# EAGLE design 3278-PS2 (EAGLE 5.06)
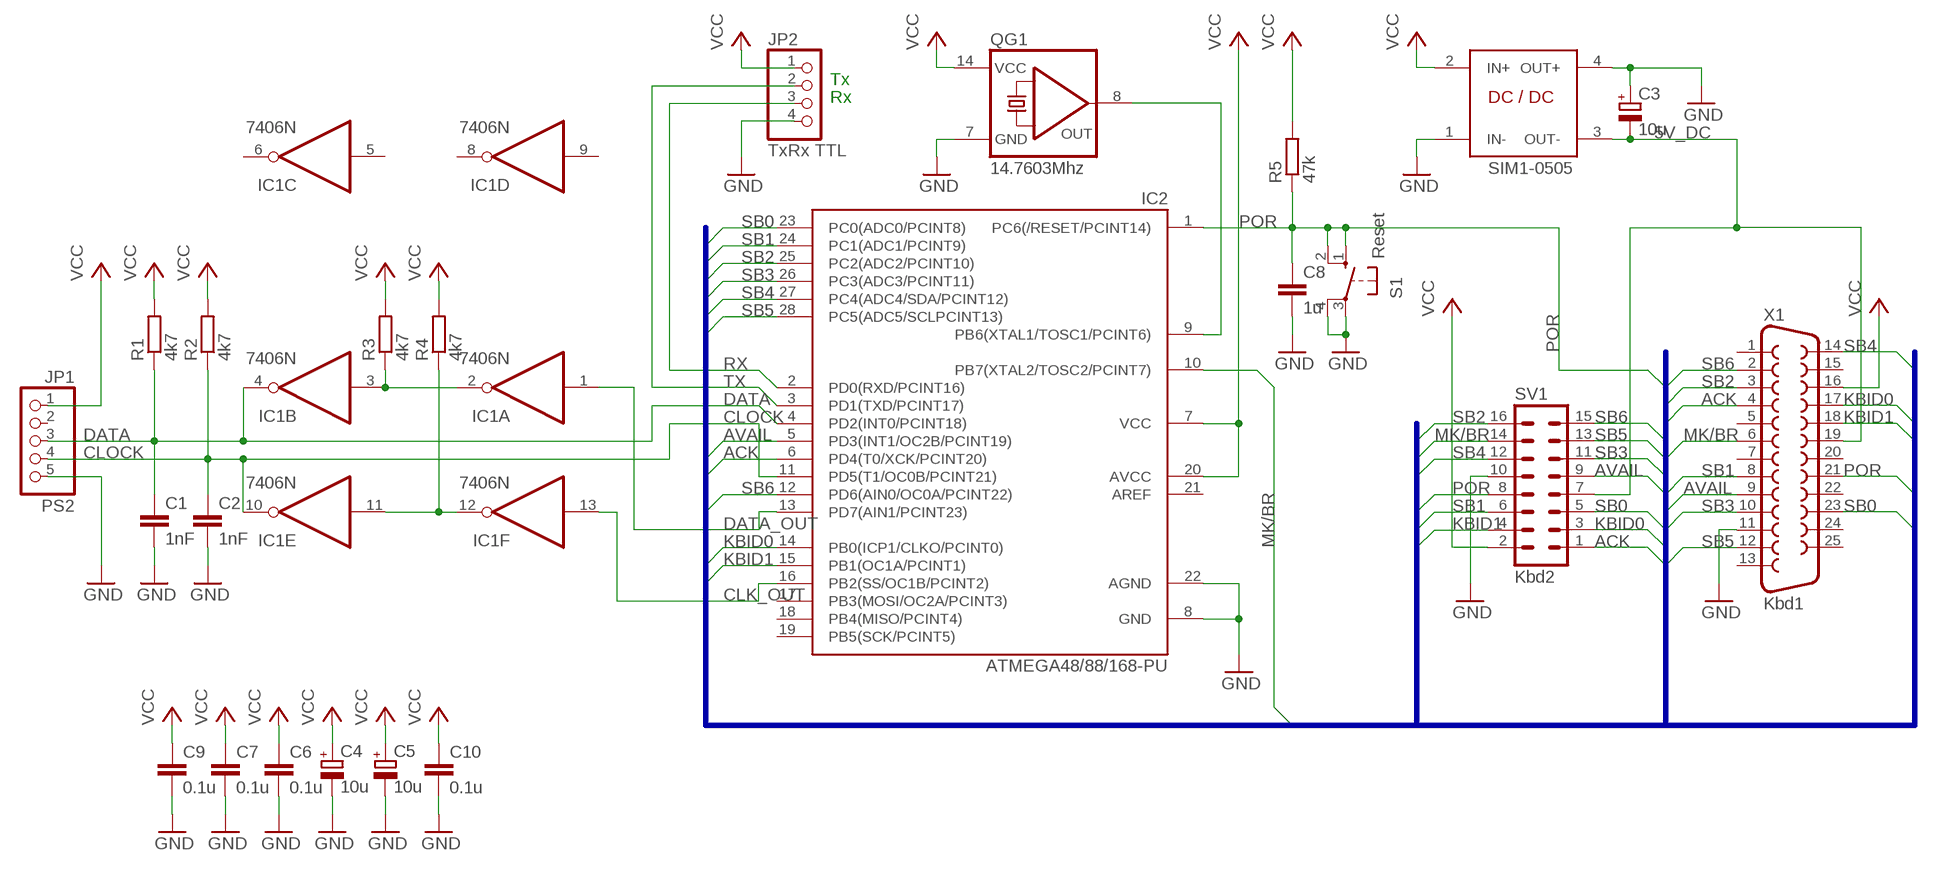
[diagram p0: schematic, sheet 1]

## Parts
C1  1nF  C-EU025_050-025X075  [C025_050-025X075]
C2  1nF  C-EU025_050-025X075  [C025_050-025X075]
C3  10u  CPOL-EUE2.5-7  [E2,5-7]
C4  10u  CPOL-EUE2.5-7  [E2,5-7]
C5  10u  CPOL-EUE2.5-7  [E2,5-7]
C6  0.1u  C-EU025_050-025X075  [C025_050-025X075]
C7  0.1u  C-EU025_050-025X075  [C025_050-025X075]
C8  1u  C-EU025_050-025X075  [C025_050-025X075]
C9  0.1u  C-EU025_050-025X075  [C025_050-025X075]
C10  0.1u  C-EU025_050-025X075  [C025_050-025X075]
IC1  7406N  [DIL14]
IC2  ATMEGA48/88/168-PU  [DIL28-3]
JP1  PS2  PINHD-1X5  [1X05]
JP2  TxRx TTL  PINHD-1X4  [1X04]
QG1  14.7603Mhz  QG5860  [DIL14S]
R1  4k7  R-EU_0207/10  [0207/10]
R2  4k7  R-EU_0207/10  [0207/10]
R3  4k7  R-EU_0207/10  [0207/10]
R4  4k7  R-EU_0207/10  [0207/10]
R5  47k  R-EU_0207/10  [0207/10]
S1  Reset  10-XX  [B3F-10XX]
SV1  Kbd2  ML16  [ML16]
U$1  SIM1-0505  SIM1-SIL4  [SIL4]
X1  Kbd1  F25HP  [F25HP]

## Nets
-5V_DC: C3.- SV1.7 U$1.3(OUT-) X1.19
ACK: IC2.6(PD4(T0/XCK/PCINT20)) SV1.1 X1.4
AVAIL: IC2.5(PD3(INT1/OC2B/PCINT19)) SV1.9 X1.9
CLK_OUT: IC1.13(F:I) IC2.16(PB2(SS/OC1B/PCINT2))
CLOCK: C2.1 IC1.10(E:O) IC2.11(PD5(T1/OC0B/PCINT21)) JP1.4 R2.1
DATA: C1.1 IC1.4(B:O) IC2.4(PD2(INT0/PCINT18)) JP1.3 R1.1
DATA_OUT: IC1.1(A:I) IC2.13(PD7(AIN1/PCINT23))
GND [power]: C1.2 C2.2 C3.+ C4.- C5.- C6.2 C7.2 C8.2 C9.2 C10.2 IC2.8(GND) IC2.22(AGND) JP1.5 JP2.4 QG1.7(GND) S1.3(P) S1.4(P1) SV1.10 U$1.1(IN-) U$1.4(OUT+) X1.11
KBID0: IC2.14(PB0(ICP1/CLKO/PCINT0)) SV1.3 X1.17
KBID1: IC2.15(PB1(OC1A/PCINT1)) SV1.4 X1.18
MK/BR: IC2.10(PB7(XTAL2/TOSC2/PCINT7)) SV1.14 X1.6
N$3: IC1.2(A:O) IC1.3(B:I) R3.1
N$4: IC1.11(E:I) IC1.12(F:O) R4.1
N$9: IC2.9(PB6(XTAL1/TOSC1/PCINT6)) QG1.8(OUT)
POR: C8.1 IC2.1(PC6(/RESET/PCINT14)) R5.1 S1.1(S) S1.2(S1) SV1.8 X1.21
RX: IC2.2(PD0(RXD/PCINT16)) JP2.3
SB0: IC2.23(PC0(ADC0/PCINT8)) SV1.5 X1.23
SB1: IC2.24(PC1(ADC1/PCINT9)) SV1.6 X1.8
SB2: IC2.25(PC2(ADC2/PCINT10)) SV1.16 X1.3
SB3: IC2.26(PC3(ADC3/PCINT11)) SV1.11 X1.10
SB4: IC2.27(PC4(ADC4/SDA/PCINT12)) SV1.12 X1.14
SB5: IC2.28(PC5(ADC5/SCLPCINT13)) SV1.13 X1.12
SB6: IC2.12(PD6(AIN0/OC0A/PCINT22)) SV1.15 X1.2
TX: IC2.3(PD1(TXD/PCINT17)) JP2.2
VCC [power]: C4.+ C5.+ C6.1 C7.1 C9.1 C10.1 IC2.7(VCC) IC2.20(AVCC) JP1.1 JP2.1 QG1.14(VCC) R1.2 R2.2 R3.2 R4.2 R5.2 SV1.2 U$1.2(IN+) X1.16
Unconnected: IC1.5(C:I) IC1.6(C:O) IC1.8(D:O) IC1.9(D:I) IC2.17(PB3(MOSI/OC2A/PCINT3)) IC2.18(PB4(MISO/PCINT4)) IC2.19(PB5(SCK/PCINT5)) IC2.21(AREF) JP1.2 X1.1 X1.5 X1.7 X1.13 X1.15 X1.20 X1.22 X1.24 X1.25

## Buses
SB[0..6],KBID[0..1],POR,ACK,MK/BR,AVAIL

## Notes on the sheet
- Tx
- Rx

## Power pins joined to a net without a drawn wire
GND: IC1.7(P:GND)
VCC: IC1.14(P:VCC)

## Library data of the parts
C1 C2 C6-C10 = rcl:C-EU: CAPACITOR, European symbol
C3-C5 = rcl:CPOL-EU: POLARIZED CAPACITOR, European symbol
IC1 = 74xx-eu:74*06: Hex INVERTER, open collector high-voltage output
IC2 = atmega8:ATMEGA48/88/168-PU
JP1 = pinhead:PINHD-1X5: PIN HEADER
JP2 = pinhead:PINHD-1X4: PIN HEADER
QG1 = crystal:QG5860: CRYSTAL RESONATOR
R1-R5 = rcl:R-EU_: RESISTOR, European symbol
S1 = switch-omron:10-XX: OMRON SWITCH
SV1 = con-harting-ml:ML16: HARTING
U$1 = hjs:SIM1-SIL4
X1 = con-subd:F25: SUB-D

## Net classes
1 power: width 0.635 mm

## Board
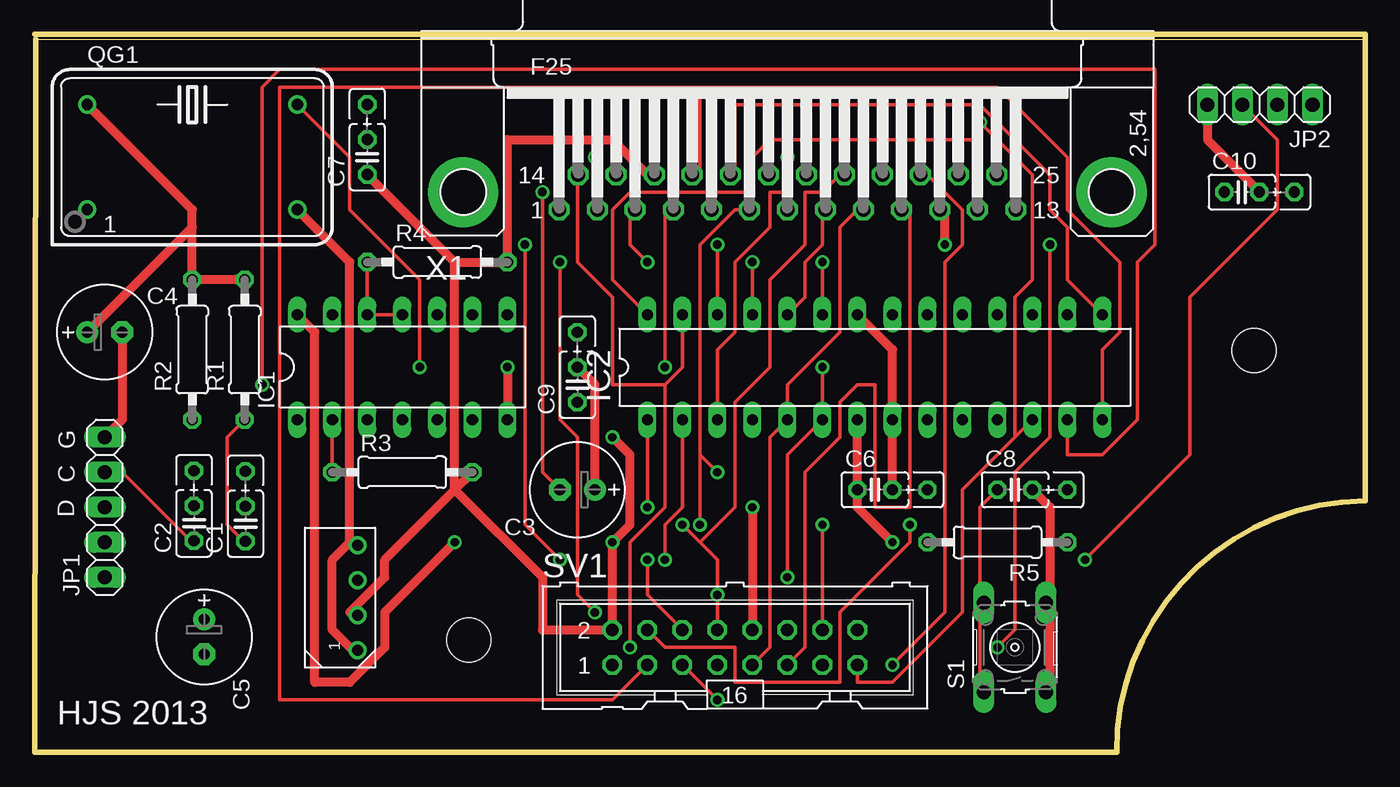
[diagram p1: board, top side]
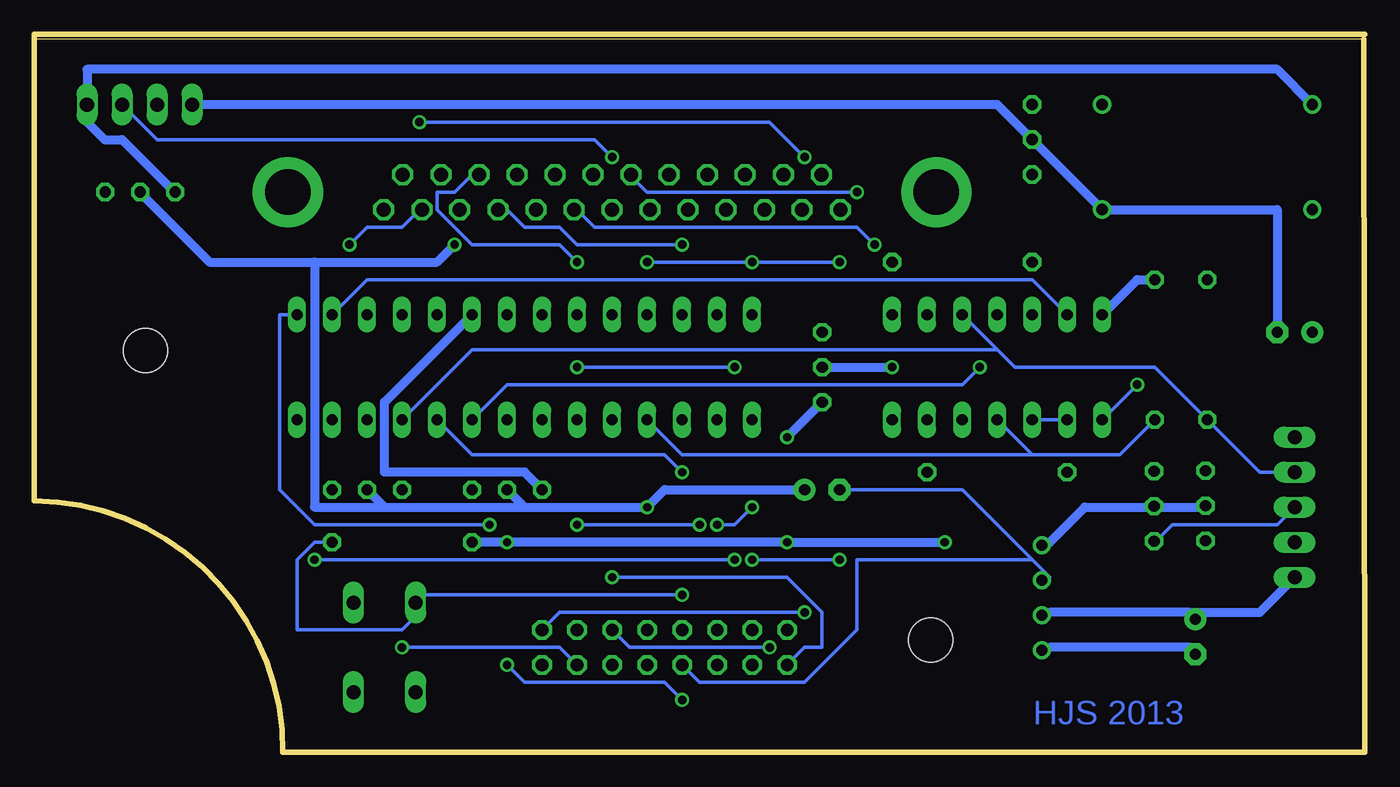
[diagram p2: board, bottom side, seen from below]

Size 96.54 x 52.07 mm. Coordinates in mm from the lower left corner, seen from the top.
Outline: 96.54,51.74 0,51.74 0.09,51.73 0.02,0 78.51,0 arc-90 96.54,18.24 96.54,52.07 0.02,52.07
Copper layers (1*16): Top 0.035mm / dielectric 1.5mm / Bottom 0.035mm
Design rules "default": minimum track width 10mil, minimum drill 24mil, track to track 8mil, track to pad 8mil, pad to pad 8mil, via to via 8mil, smd to smd 8mil, copper to edge 40mil, drill to drill 8mil, minimum pad ring 10mil, minimum via ring 8mil, stop-mask expansion 4mil, vias tented up to drill 0mil, thermal gap 10mil
Holes 3.2 mm at 31.5,8.16 88.5,29.16
tRestrict: area 27.7,4.4 to 35.3,12; area 84.7,25.4 to 92.3,33
bRestrict: area 26.4,0 to 36.6,5.1; area 26.4,3.1 to 36.6,13.2; area 83.4,24.1 to 93.6,34.2; area 91.6,24.2 to 96.7,34.3

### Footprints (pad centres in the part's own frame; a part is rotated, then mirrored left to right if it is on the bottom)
C025_050-025X075 = drill 0.813 octagon: 1 -1.27,0; 2 1.27,0; 3 3.81,0
E2,5-7 = drill 0.813 pad 1.6 round: + -1.27,0 | drill 0.813 pad 1.6 octagon: - 1.27,0
DIL14 = drill 0.813 long: 1 -7.62,-3.81; 2 -5.08,-3.81; 3 -2.54,-3.81; 4 0,-3.81; 5 2.54,-3.81; 6 5.08,-3.81; 7 7.62,-3.81; 8 7.62,3.81; 9 5.08,3.81; 10 2.54,3.81; 11 0,3.81; 12 -2.54,3.81; 13 -5.08,3.81; 14 -7.62,3.81
DIL28-3 = drill 0.813 long: 1 -16.51,-3.81; 2 -13.97,-3.81; 3 -11.43,-3.81; 4 -8.89,-3.81; 5 -6.35,-3.81; 6 -3.81,-3.81; 7 -1.27,-3.81; 8 1.27,-3.81; 9 3.81,-3.81; 10 6.35,-3.81; 11 8.89,-3.81; 12 11.43,-3.81; 13 13.97,-3.81; 14 16.51,-3.81; 15 16.51,3.81; 16 13.97,3.81; 17 11.43,3.81; 18 8.89,3.81; 19 6.35,3.81; 20 3.81,3.81; 21 1.27,3.81; 22 -1.27,3.81; 23 -3.81,3.81; 24 -6.35,3.81; 25 -8.89,3.81; 26 -11.43,3.81; 27 -13.97,3.81; 28 -16.51,3.81
1X05 = drill 1.016 long: 1 -5.08,0; 2 -2.54,0; 3 0,0; 4 2.54,0; 5 5.08,0
1X04 = drill 1.016 long: 1 -3.81,0; 2 -1.27,0; 3 1.27,0; 4 3.81,0
DIL14S = drill 0.813 round: 1 -7.62,-3.81; 7 7.62,-3.81; 8 7.62,3.81; 14 -7.62,3.81
0207/10 = drill 0.813 octagon: 1 -5.08,0; 2 5.08,0
B3F-10XX = drill 1.016 long: 1 -3.251,2.261; 2 3.251,2.261; 3 -3.251,-2.261; 4 3.251,-2.261
ML16 = drill 0.914 octagon: 1 -8.89,-1.27; 2 -8.89,1.27; 3 -6.35,-1.27; 4 -6.35,1.27; 5 -3.81,-1.27; 6 -3.81,1.27; 7 -1.27,-1.27; 8 -1.27,1.27; 9 1.27,-1.27; 10 1.27,1.27; 11 3.81,-1.27; 12 3.81,1.27; 13 6.35,-1.27; 14 6.35,1.27; 15 8.89,-1.27; 16 8.89,1.27
SIL4 = drill 0.8 round: 1 -3.81,0; 2 -1.27,0; 3 1.27,0; 4 3.81,0
F25HP = drill 1.016 octagon: 1 -16.561,-1.27; 2 -13.792,-1.27; 3 -11.049,-1.27; 4 -8.28,-1.27; 5 -5.512,-1.27; 6 -2.769,-1.27; 7 0,-1.27; 8 2.769,-1.27; 9 5.512,-1.27; 10 8.28,-1.27; 11 11.049,-1.27; 12 13.792,-1.27; 13 16.561,-1.27; 14 -15.189,1.27; 15 -12.421,1.27; 16 -9.652,1.27; 17 -6.909,1.27; 18 -4.14,1.27; 19 -1.372,1.27; 20 1.372,1.27; 21 4.14,1.27; 22 6.909,1.27; 23 9.652,1.27; 24 12.421,1.27; 25 15.189,1.27 | drill 3.302 pad 5.08 round: G1 -23.52,0; G2 23.52,0

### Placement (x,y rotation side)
C1  15.31,16.59 90 top
C2  11.57,16.62 90 top
C3  39.39,19.05 180 top
C4  5.1,30.48 0 top
C5  12.31,8.38 270 top
C6  60.98,19.05 0 top
C7  24.15,43.18 90 top
C8  71.14,19.05 0 top
C9  39.39,26.67 90 top
C10  87.6,40.64 0 top
IC1  26.69,27.94 0 top
IC2  60.98,27.94 0 top
JP1  5.1,17.78 90 top
JP2  88.92,46.99 180 top
QG1  11.45,43.18 0 top
R1  15.26,29.21 90 top
R2  11.45,29.21 90 top
R3  26.69,20.32 0 top
R4  29.23,35.56 0 top
R5  69.87,15.24 180 top
S1  71.14,7.62 90 top
SV1  50.82,7.62 0 top
U$1  23.44,11.22 90 top
X1  54.63,40.64 0 top

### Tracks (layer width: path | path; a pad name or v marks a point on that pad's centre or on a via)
-5V_DC  (via drill 0.61)
  Top 0.254: v36.85,40.64 36.85,20.32 C3.-
  Bottom 0.254: 24.15,13.97 29.23,19.05 C3.- | 24.15,13.97 22.88,12.7 U$1.3 | SV1.7 48.28,5.08 40.66,5.08 36.85,8.89 36.85,13.97 24.15,13.97 | v36.85,40.64 52.09,40.64 53.36,41.91 X1.19
ACK  (via drill 0.61)
  Top 0.254: v54.63,12.7 54.63,21.59 IC2.6 v57.17,27.94 | v45.74,27.94 45.74,39.37 X1.4
  Bottom 0.254: v54.63,12.7 41.93,12.7 39.39,10.16 39.39,7.62 40.66,7.62 SV1.1 | v57.17,27.94 v45.74,27.94
AVAIL
  Top 0.254: SV1.9 53.36,7.62 53.36,22.86 IC2.5 54.63,26.67 58.44,30.48 58.44,38.1 59.71,39.37 X1.9
CLK_OUT
  Bottom 0.254: IC1.13 24.15,34.29 72.41,34.29 IC2.16
CLOCK
  Top 0.254: JP1.4 6.37,20.32 11.45,15.24 C2.1
  Bottom 0.254: JP1.4 7.64,20.32 R2.1 15.26,27.94 25.42,27.94 26.69,29.21 | 26.69,29.21 IC1.10 | IC2.11 64.79,29.21 26.69,29.21
DATA
  Top 0.254: R1.1 13.99,22.86 13.99,16.51 15.26,15.24 C1.1
  Bottom 0.254: 24.15,21.59 IC1.4 | 24.15,21.59 17.8,21.59 R1.1 | IC2.4 49.55,21.59 24.15,21.59 | JP1.3 6.37,16.51 13.99,16.51 15.26,15.24 C1.1
DATA_OUT  (via drill 0.61)
  Top 0.254: v16.53,26.67 16.53,48.26 17.8,49.53 81.3,49.53 81.3,36.83 80.03,35.56 80.03,24.13 77.49,21.59 74.95,21.59 IC2.13
  Bottom 0.254: IC1.1 v16.53,26.67
GND  (via drill 0.61)
  Top 0.635: JP1.5 6.37,24.13 C4.- | QG1.7 22.88,35.56 22.88,15.24 | 22.88,15.24 21.61,13.97 21.61,8.89 22.88,7.62 U$1.1 | 22.88,15.24 U$1.4 | JP2.4 85.11,44.45 88.92,40.64 C10.2 | v66.06,36.83 66.06,39.37 X1.11 | C8.2 73.68,17.78 73.68,11.43 S1.4 73.68,10.16 73.68,5.08 S1.3 | C6.2 IC2.8 62.25,29.21 IC2.22 | v34.31,27.94 IC1.7 | v52.09,17.78 SV1.10 | C9.2 40.66,26.67 C3.+
  Bottom 0.635: U$1.1 22.88,7.62 12.72,7.62 C5.- | 15.26,17.78 20.34,17.78 22.88,15.24 U$1.4 | 15.26,17.78 11.45,17.78 C2.2 | 15.26,17.78 C1.2 | C4.- 6.37,39.37 QG1.7 C7.2 26.69,46.99 JP2.4 | v66.06,36.83 67.33,35.56 76.22,35.56 | 76.22,35.56 83.84,35.56 88.92,40.64 C10.2 | C9.2 v34.31,27.94 | C3.+ 50.82,19.05 v52.09,17.78 60.98,17.78 | 60.98,17.78 C6.2 | 71.14,17.78 C8.2 | 71.14,17.78 60.98,17.78 | 76.22,35.56 76.22,17.78 71.14,17.78
KBID0
  Top 0.254: IC2.14 77.49,29.21 78.76,30.48 78.76,35.56 74.95,39.37 74.95,43.18 69.87,48.26 48.28,48.26 | 48.28,48.26 48.28,41.91 X1.17 | SV1.3 41.93,3.81 17.8,3.81 17.8,48.26 48.28,48.26
KBID1  (via drill 0.61)
  Top 0.254: IC2.15 74.95,34.29 74.95,38.1 73.68,39.37 73.68,41.91 68.6,46.99 50.82,46.99 50.82,41.91 X1.18 | SV1.4 45.74,7.62 50.82,7.62 50.82,5.08 58.44,5.08 58.44,10.16 63.52,15.24 v63.52,16.51
  Bottom 0.254: v63.52,16.51 76.22,16.51 78.76,19.05 78.76,31.75 IC2.15
MK/BR  (via drill 0.61)
  Top 0.254: 48.28,21.59 v49.55,20.32 | 48.28,21.59 48.28,36.83 50.82,39.37 X1.6 52.09,39.37 | SV1.14 v57.17,16.51 | v48.28,16.51 48.28,21.59
  Bottom 0.254: IC2.10 64.79,21.59 50.82,21.59 v49.55,20.32 | v57.17,16.51 v48.28,16.51
N$3
  Top 0.254: R3.1 IC1.2
  Bottom 0.254: IC1.2 IC1.3
N$4
  Top 0.254: IC1.11 IC1.12 R4.1
N$9  (via drill 0.61)
  Top 0.254: QG1.8 22.88,43.18 22.88,39.37 27.96,34.29 v27.96,27.94
  Bottom 0.254: v27.96,27.94 29.23,26.67 62.25,26.67 IC2.9
POR  (via drill 0.61)
  Top 0.254: C8.1 68.6,17.78 68.6,11.43 S1.2 68.6,10.16 68.6,5.08 S1.1 | v44.47,17.78 IC2.1 | 48.28,15.24 49.55,13.97 v49.55,11.43 SV1.8 | 48.28,15.24 v47.01,16.51 | 48.28,15.24 50.82,17.78 50.82,25.4 53.36,27.94 53.36,34.29 55.9,36.83 55.9,40.64 57.17,40.64 58.44,41.91 X1.21
  Bottom 0.254: R5.1 76.22,15.24 77.49,13.97 77.49,8.89 69.87,8.89 68.6,10.16 S1.2 68.6,11.43 v49.55,11.43 | v44.47,17.78 45.74,16.51 v47.01,16.51
RX  (via drill 0.61)
  Top 0.254: IC2.2 47.01,17.78 45.74,16.51 v45.74,13.97 | v76.22,13.97 83.84,21.59 83.84,33.02 90.19,39.37 90.19,44.45 JP2.3
  Bottom 0.254: v45.74,13.97 v76.22,13.97
SB0  (via drill 0.61)
  Top 0.254: v57.17,35.56 IC2.23 | SV1.5 v49.55,3.81 | v62.25,6.35 66.06,10.16 66.06,35.56 67.33,36.83 67.33,39.37 64.79,41.91 X1.23
  Bottom 0.254: v57.17,35.56 58.44,36.83 64.79,36.83 67.33,39.37 67.33,40.64 66.06,40.64 64.79,41.91 X1.23 | v49.55,3.81 50.82,5.08 60.98,5.08 v62.25,6.35
SB1  (via drill 0.61)
  Top 0.254: IC2.24 55.9,33.02 55.9,35.56 57.17,36.83 57.17,39.37 X1.8 | SV1.6 44.47,11.43 v44.47,13.97 | v38.12,13.97 35.58,16.51 v35.58,36.83
  Bottom 0.254: v38.12,13.97 v44.47,13.97 | v35.58,36.83 36.85,38.1 55.9,38.1 57.17,39.37 X1.8
SB2  (via drill 0.61)
  Top 0.254: v52.09,35.56 IC2.25 | v44.47,35.56 43.2,36.83 43.2,39.37 X1.3 | v40.66,10.16 39.39,11.43 39.39,22.86 38.12,24.13 v38.12,35.56
  Bottom 0.254: v52.09,35.56 v44.47,35.56 v38.12,35.56 | SV1.16 58.44,10.16 v40.66,10.16
SB3  (via drill 0.61)
  Top 0.254: v49.55,36.83 IC2.26 | SV1.11 55.9,7.62 55.9,20.32 58.44,22.86 58.44,25.4 59.71,26.67 60.98,26.67 60.98,17.78 63.52,17.78 63.52,39.37 X1.10
  Bottom 0.254: v49.55,36.83 57.17,36.83 58.44,38.1 60.98,38.1 62.25,39.37 X1.10
SB4  (via drill 0.61)
  Top 0.254: IC2.27 47.01,27.94 45.74,26.67 | 45.74,26.67 41.93,26.67 41.93,33.02 39.39,35.56 39.39,41.91 X1.14 | v43.2,7.62 43.2,15.24 45.74,17.78 45.74,26.67
  Bottom 0.254: SV1.12 53.36,7.62 v43.2,7.62
SB5  (via drill 0.61)
  Top 0.254: IC2.28 41.93,34.29 41.93,39.37 43.2,40.64 52.09,40.64 52.09,43.18 53.36,44.45 68.6,44.45 68.6,39.37 X1.12 | v69.87,7.62 71.14,8.89 71.14,20.32 73.68,22.86 v73.68,36.83
  Bottom 0.254: SV1.13 58.44,7.62 v69.87,7.62 | v73.68,36.83 72.41,38.1 69.87,38.1 68.6,39.37 X1.12
SB6  (via drill 0.61)
  Top 0.254: 71.14,22.86 67.33,19.05 67.33,10.16 62.25,5.08 59.71,5.08 SV1.15 | 71.14,22.86 IC2.12 | v40.66,43.18 40.66,39.37 X1.2 | v68.6,45.72 72.41,41.91 72.41,34.29 71.14,33.02 71.14,22.86
  Bottom 0.254: v40.66,43.18 43.2,45.72 v68.6,45.72
TX  (via drill 0.61)
  Top 0.254: IC2.3 49.55,29.21 50.82,30.48 50.82,35.56 53.36,38.1 53.36,40.64 54.63,40.64 v54.63,43.18
  Bottom 0.254: v54.63,43.18 55.9,44.45 87.65,44.45 JP2.2
VCC  (via drill 0.61)
  Top 0.635: IC2.7 C6.1 59.71,17.78 v62.25,15.24 | v41.93,22.86 43.2,21.59 43.2,16.51 v41.93,15.24 SV1.2 36.85,8.89 36.85,12.7 30.5,19.05 | 30.5,19.05 25.42,13.97 25.42,12.7 22.88,10.16 U$1.2 | 30.5,19.05 R3.2 | 30.5,35.56 R4.2 34.31,44.45 41.93,44.45 44.47,41.91 X1.16 | 30.5,19.05 30.5,35.56 | 30.5,35.56 C7.1 | QG1.14 11.45,39.37 11.45,38.1 | 11.45,38.1 R2.2 R1.2 | 11.45,38.1 C4.+ | v30.5,15.24 25.42,10.16 25.42,7.62 22.88,5.08 20.34,5.08 20.34,30.48 IC1.14
  Bottom 0.635: R5.2 v62.25,15.24 v41.93,15.24 v30.5,15.24 | IC2.20 71.14,25.4 71.14,20.32 60.98,20.32 C6.1 | v41.93,22.86 C9.1 | 12.72,10.16 22.88,10.16 U$1.2 | JP1.1 7.64,10.16 12.72,10.16 | C5.+ 12.72,10.16 | C10.1 86.38,40.64 90.19,44.45 91.46,44.45 92.73,45.72 JP2.1 92.73,49.53 6.37,49.53 QG1.14 | IC1.14 16.53,34.29 R1.2

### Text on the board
Bottom: HJS 2013
tNames: G | C | D | HJS 2013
